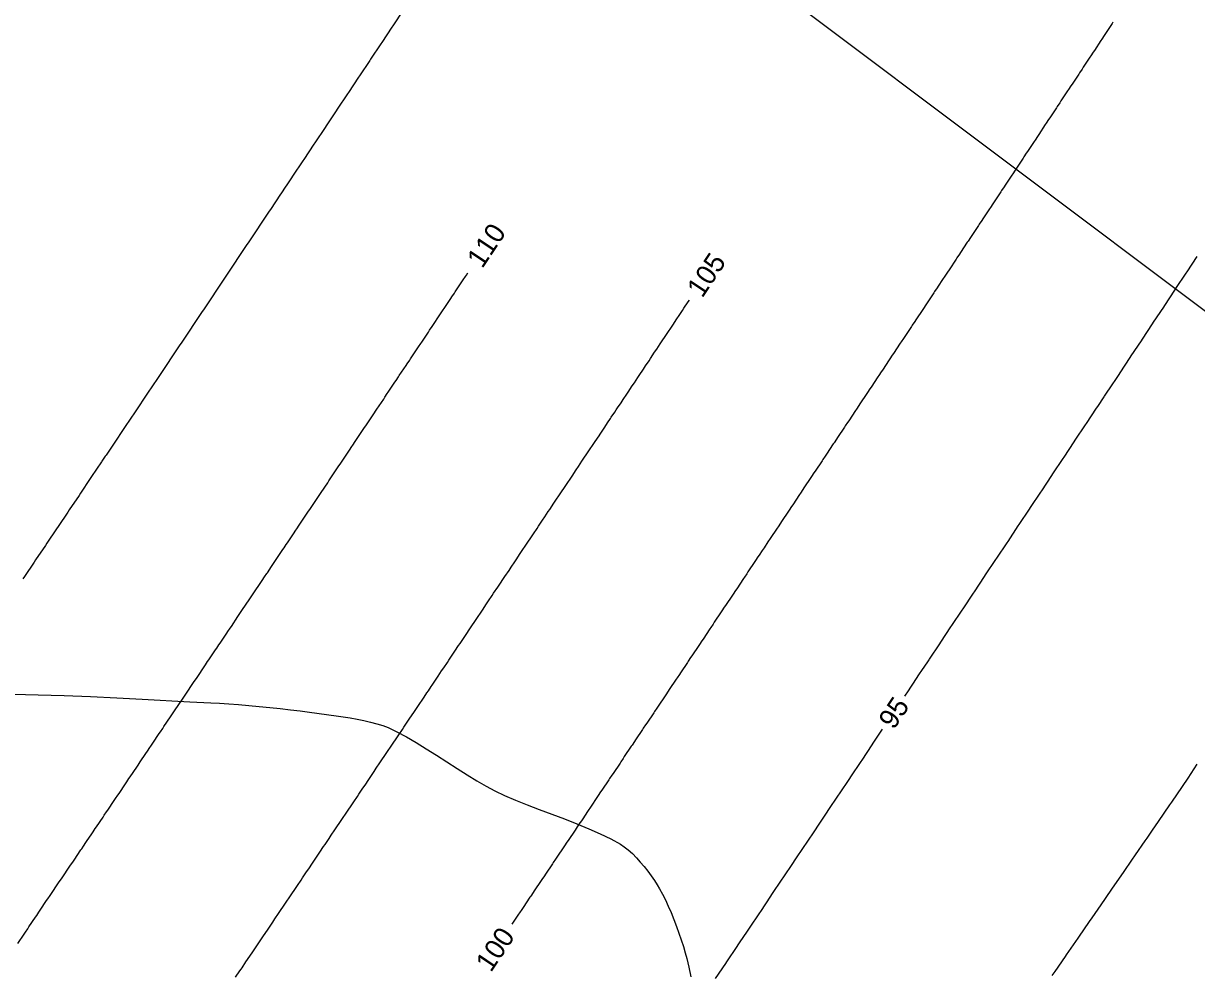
# Model space of a CAD drawing. Extents: x 1752788 to 1754108, y 472767 to 474963.
# Drawn here: x 1753280 to 1753338.7, y 473789.9 to 473837.4 of the extents above; entities that cross this region are included whole.
import ezdxf

# ---------------------------------------------------------------- set-up
doc = ezdxf.new("R2010")
doc.units = 0
for name, color, linetype in [('D_Roadway_Centerline', 7, 'Continuous'), ('D_Slope_ClearingLimitLine', 7, 'Continuous'), ('Default', 7, 'Continuous'), ('M_Drainage_Ditch_Line', 7, 'Continuous'), ('S_Contours_Major', 7, 'Continuous')]:
    doc.layers.add(name, color=color, linetype=linetype)

msp = doc.modelspace()

# ---------------------------------------------------------------- linework, layer by layer
at = {"layer": 'D_Roadway_Centerline'}
msp.add_arc((1748084.974, 477769.754), 6500, 316.3419444, 334.4169444, dxfattribs=at)
at = {"layer": 'D_Slope_ClearingLimitLine'}
msp.add_lwpolyline([(1753331.481, 473789.723), (1753331.626, 473789.934), (1753332.145, 473790.688), (1753332.2, 473790.768), (1753332.774, 473791.602), (1753332.81, 473791.653), (1753333.349, 473792.436), (1753333.474, 473792.618), (1753333.923, 473793.27), (1753334.139, 473793.583), (1753334.498, 473794.104), (1753334.803, 473794.548), (1753335.072, 473794.938), (1753335.468, 473795.513), (1753335.646, 473795.772), (1753336.132, 473796.478), (1753336.221, 473796.606), (1753336.495, 473797.004), (1753336.795, 473797.44), (1753336.797, 473797.443), (1753337.369, 473798.274), (1753337.461, 473798.408), (1753338, 473799.19), (1753338.276, 473799.608), (1753338.723, 473800.31)], dxfattribs=at)
at = {"layer": 'Default'}
msp.add_line((1753227.691, 473906.713), (1753342.696, 473820.324), dxfattribs=at)
at = {"layer": 'M_Drainage_Ditch_Line'}
msp.add_lwpolyline([(1753279.464, 473803.81), (1753280.738, 473803.789), (1753282.043, 473803.749), (1753283.358, 473803.696), (1753284.664, 473803.633), (1753285.939, 473803.567), (1753288.317, 473803.438), (1753289.381, 473803.386), (1753289.808, 473803.363), (1753290.272, 473803.332), (1753290.763, 473803.295), (1753291.274, 473803.251), (1753291.797, 473803.203), (1753292.324, 473803.15), (1753292.847, 473803.095), (1753293.357, 473803.038), (1753293.846, 473802.98), (1753294.307, 473802.921), (1753295.652, 473802.736), (1753295.993, 473802.685), (1753296.341, 473802.629), (1753296.691, 473802.567), (1753297.035, 473802.498), (1753297.369, 473802.422), (1753297.686, 473802.337), (1753297.98, 473802.243), (1753298.246, 473802.139), (1753298.691, 473801.926), (1753299.162, 473801.673), (1753299.653, 473801.388), (1753300.158, 473801.078), (1753300.671, 473800.754), (1753301.698, 473800.096), (1753302.199, 473799.778), (1753302.685, 473799.481), (1753303.149, 473799.212), (1753303.585, 473798.98), (1753304.076, 473798.748), (1753304.619, 473798.515), (1753305.201, 473798.281), (1753305.81, 473798.046), (1753307.065, 473797.569), (1753307.687, 473797.325), (1753308.29, 473797.078), (1753308.863, 473796.827), (1753309.392, 473796.57), (1753309.868, 473796.309), (1753310.064, 473796.177), (1753310.265, 473796.017), (1753310.467, 473795.832), (1753310.668, 473795.629), (1753310.865, 473795.41), (1753311.056, 473795.183), (1753311.239, 473794.95), (1753311.41, 473794.717), (1753311.568, 473794.489), (1753311.71, 473794.271), (1753311.834, 473794.067), (1753311.977, 473793.806), (1753312.121, 473793.517), (1753312.265, 473793.205), (1753312.407, 473792.877), (1753312.544, 473792.537), (1753312.676, 473792.192), (1753312.8, 473791.847), (1753312.915, 473791.508), (1753313.019, 473791.18), (1753313.11, 473790.87), (1753313.187, 473790.582), (1753313.289, 473790.142), (1753313.388, 473789.663)], dxfattribs=at)
at = {"layer": 'S_Contours_Major'}
for points in [[(1753298.996, 473838.055), (1753298.482, 473837.282), (1753298.439, 473837.216), (1753297.926, 473836.445), (1753297.881, 473836.378), (1753297.369, 473835.608), (1753297.324, 473835.539), (1753296.813, 473834.771), (1753296.766, 473834.701), (1753296.256, 473833.934), (1753296.208, 473833.863), (1753295.699, 473833.098), (1753295.651, 473833.025), (1753295.142, 473832.261), (1753295.093, 473832.187), (1753294.585, 473831.424), (1753294.534, 473831.349), (1753294.027, 473830.588), (1753293.976, 473830.511), (1753293.47, 473829.751), (1753293.418, 473829.673), (1753293.151, 473829.273), (1753293.131, 473829.243), (1753292.883, 473828.871), (1753292.864, 473828.843), (1753292.354, 473828.079), (1753292.3, 473827.998), (1753291.797, 473827.243), (1753291.742, 473827.16), (1753291.239, 473826.407), (1753291.183, 473826.323), (1753290.68, 473825.571), (1753290.624, 473825.486), (1753290.122, 473824.735), (1753290.064, 473824.648), (1753289.564, 473823.899), (1753289.505, 473823.811), (1753289.005, 473823.063), (1753288.946, 473822.974), (1753288.446, 473822.227), (1753288.386, 473822.137), (1753287.888, 473821.392), (1753287.826, 473821.3), (1753287.329, 473820.556), (1753287.266, 473820.463), (1753286.77, 473819.721), (1753286.706, 473819.626), (1753286.21, 473818.885), (1753286.146, 473818.789), (1753285.651, 473818.05), (1753285.586, 473817.953), (1753285.091, 473817.214), (1753285.025, 473817.116), (1753284.532, 473816.379), (1753284.465, 473816.279), (1753284.135, 473815.788), (1753284.094, 473815.727), (1753283.929, 473815.48), (1753283.912, 473815.455), (1753283.412, 473814.709), (1753283.343, 473814.607), (1753282.852, 473813.874), (1753282.782, 473813.77), (1753282.291, 473813.039), (1753282.221, 473812.934), (1753281.731, 473812.204), (1753281.66, 473812.098), (1753281.17, 473811.369), (1753281.099, 473811.262), (1753280.61, 473810.534), (1753280.537, 473810.426), (1753280.049, 473809.699), (1753279.976, 473809.59)], [(1753334.516, 473837.452), (1753334.475, 473837.39), (1753334.145, 473836.891), (1753334.084, 473836.797), (1753333.96, 473836.609), (1753333.918, 473836.547), (1753333.588, 473836.047), (1753333.526, 473835.953), (1753333.403, 473835.766), (1753333.362, 473835.704), (1753333.031, 473835.204), (1753332.969, 473835.11), (1753332.846, 473834.924), (1753332.805, 473834.861), (1753332.474, 473834.36), (1753332.412, 473834.267), (1753332.289, 473834.081), (1753332.248, 473834.019), (1753331.916, 473833.517), (1753331.855, 473833.424), (1753331.732, 473833.238), (1753331.691, 473833.176), (1753331.358, 473832.674), (1753331.297, 473832.581), (1753331.174, 473832.395), (1753331.133, 473832.334), (1753330.8, 473831.83), (1753330.739, 473831.738), (1753330.617, 473831.553), (1753330.576, 473831.491), (1753330.243, 473830.987), (1753330.181, 473830.895), (1753330.059, 473830.71), (1753330.019, 473830.649), (1753329.684, 473830.144), (1753329.623, 473830.052), (1753329.502, 473829.868), (1753329.461, 473829.806), (1753329.126, 473829.301), (1753329.065, 473829.209), (1753328.944, 473829.026), (1753328.903, 473828.964), (1753328.568, 473828.458), (1753328.507, 473828.367), (1753328.386, 473828.183), (1753328.345, 473828.122), (1753328.009, 473827.616), (1753327.949, 473827.524), (1753327.828, 473827.341), (1753327.787, 473827.28), (1753327.451, 473826.773), (1753327.39, 473826.682), (1753327.269, 473826.499), (1753327.229, 473826.439), (1753326.892, 473825.93), (1753326.832, 473825.839), (1753326.711, 473825.657), (1753326.671, 473825.597), (1753326.313, 473825.057), (1753326.237, 473824.944), (1753326.103, 473824.741), (1753325.99, 473824.571), (1753325.774, 473824.245), (1753325.714, 473824.155), (1753325.594, 473823.974), (1753325.554, 473823.914), (1753325.215, 473823.403), (1753325.155, 473823.313), (1753325.035, 473823.132), (1753324.995, 473823.072), (1753324.655, 473822.561), (1753324.596, 473822.471), (1753324.476, 473822.291), (1753324.436, 473822.231), (1753324.096, 473821.718), (1753324.036, 473821.629), (1753323.917, 473821.449), (1753323.877, 473821.389), (1753323.536, 473820.876), (1753323.477, 473820.787), (1753323.358, 473820.608), (1753323.318, 473820.548), (1753322.977, 473820.034), (1753322.917, 473819.945), (1753322.799, 473819.766), (1753322.759, 473819.707), (1753322.417, 473819.192), (1753322.358, 473819.103), (1753322.239, 473818.925), (1753322.2, 473818.866), (1753321.857, 473818.35), (1753321.798, 473818.261), (1753321.68, 473818.084), (1753321.64, 473818.025), (1753321.297, 473817.508), (1753321.238, 473817.42), (1753321.12, 473817.243), (1753321.081, 473817.184), (1753320.736, 473816.666), (1753320.678, 473816.578), (1753320.56, 473816.402), (1753320.521, 473816.343), (1753320.176, 473815.825), (1753320.117, 473815.737), (1753320, 473815.56), (1753319.961, 473815.501), (1753319.616, 473814.983), (1753319.557, 473814.895), (1753319.439, 473814.719), (1753319.4, 473814.66), (1753319.055, 473814.142), (1753318.996, 473814.054), (1753318.878, 473813.877), (1753318.839, 473813.818), (1753318.494, 473813.301), (1753318.435, 473813.212), (1753318.317, 473813.035), (1753318.278, 473812.976), (1753317.933, 473812.459), (1753317.874, 473812.371), (1753317.756, 473812.193), (1753317.717, 473812.134), (1753317.363, 473811.604), (1753317.25, 473811.434), (1753317.06, 473811.15), (1753316.966, 473811.008), (1753316.811, 473810.777), (1753316.752, 473810.688), (1753316.634, 473810.511), (1753316.595, 473810.452), (1753316.25, 473809.936), (1753316.191, 473809.847), (1753316.073, 473809.671), (1753316.033, 473809.612), (1753315.688, 473809.095), (1753315.629, 473809.006), (1753315.512, 473808.83), (1753315.472, 473808.771), (1753315.127, 473808.254), (1753315.068, 473808.166), (1753314.95, 473807.989), (1753314.911, 473807.93), (1753314.565, 473807.413), (1753314.506, 473807.325), (1753314.389, 473807.149), (1753314.349, 473807.09), (1753314.003, 473806.572), (1753313.944, 473806.484), (1753313.827, 473806.308), (1753313.788, 473806.25), (1753313.441, 473805.731), (1753313.382, 473805.644), (1753313.265, 473805.468), (1753313.226, 473805.409), (1753312.879, 473804.891), (1753312.82, 473804.803), (1753312.703, 473804.628), (1753312.664, 473804.569), (1753312.317, 473804.05), (1753312.258, 473803.963), (1753312.141, 473803.787), (1753312.102, 473803.729), (1753311.754, 473803.21), (1753311.696, 473803.122), (1753311.579, 473802.947), (1753311.54, 473802.889), (1753311.192, 473802.369), (1753311.133, 473802.282), (1753311.016, 473802.107), (1753310.977, 473802.049), (1753310.629, 473801.529), (1753310.571, 473801.442), (1753310.454, 473801.267), (1753310.415, 473801.209), (1753310.066, 473800.689), (1753310.008, 473800.602), (1753309.891, 473800.427), (1753309.852, 473800.369), (1753309.503, 473799.849), (1753309.445, 473799.762), (1753309.328, 473799.588), (1753309.29, 473799.53), (1753308.94, 473799.009), (1753308.882, 473798.922), (1753308.765, 473798.747), (1753308.726, 473798.689), (1753308.371, 473798.159), (1753308.253, 473797.984), (1753308.227, 473797.945), (1753307.982, 473797.579), (1753307.917, 473797.482), (1753307.794, 473797.3), (1753307.657, 473797.095), (1753307.599, 473797.008), (1753307.251, 473796.489), (1753307.192, 473796.401), (1753307.074, 473796.226), (1753307.034, 473796.167), (1753306.687, 473795.65), (1753306.628, 473795.562), (1753306.51, 473795.385), (1753306.47, 473795.326), (1753306.123, 473794.81), (1753306.064, 473794.722), (1753305.945, 473794.545), (1753305.906, 473794.486), (1753305.56, 473793.971), (1753305.5, 473793.882), (1753305.381, 473793.705), (1753305.341, 473793.646), (1753304.996, 473793.131), (1753304.936, 473793.042), (1753304.817, 473792.865), (1753304.777, 473792.805), (1753304.439, 473792.302)], [(1753324.097, 473803.712), (1753324.162, 473803.809), (1753324.213, 473803.885), (1753324.724, 473804.651), (1753324.775, 473804.727), (1753325.021, 473805.096), (1753325.039, 473805.123), (1753325.313, 473805.534), (1753325.333, 473805.563), (1753325.849, 473806.336), (1753325.899, 473806.412), (1753326.411, 473807.18), (1753326.461, 473807.254), (1753326.973, 473808.023), (1753327.022, 473808.096), (1753327.535, 473808.867), (1753327.584, 473808.939), (1753328.097, 473809.71), (1753328.145, 473809.782), (1753328.659, 473810.553), (1753328.706, 473810.624), (1753329.219, 473811.395), (1753329.267, 473811.467), (1753329.78, 473812.238), (1753329.828, 473812.311), (1753330.341, 473813.08), (1753330.389, 473813.154), (1753330.901, 473813.923), (1753330.95, 473813.997), (1753331.461, 473814.766), (1753331.511, 473814.84), (1753332.021, 473815.608), (1753332.071, 473815.684), (1753332.581, 473816.451), (1753332.632, 473816.527), (1753333.141, 473817.294), (1753333.192, 473817.371), (1753333.701, 473818.137), (1753333.752, 473818.215), (1753334.072, 473818.696), (1753334.098, 473818.736), (1753334.292, 473819.028), (1753334.306, 473819.049), (1753334.82, 473819.824), (1753334.872, 473819.902), (1753335.379, 473820.667), (1753335.432, 473820.746), (1753335.939, 473821.51), (1753335.991, 473821.59), (1753336.498, 473822.354), (1753336.551, 473822.434), (1753337.057, 473823.197), (1753337.11, 473823.278), (1753337.615, 473824.041), (1753337.669, 473824.122), (1753338.174, 473824.885), (1753338.228, 473824.967), (1753338.733, 473825.728)], [(1753279.713, 473791.334), (1753280.032, 473791.807), (1753280.099, 473791.906), (1753280.21, 473792.07), (1753280.276, 473792.169), (1753280.596, 473792.643), (1753280.663, 473792.741), (1753280.773, 473792.905), (1753280.84, 473793.004), (1753281.16, 473793.479), (1753281.227, 473793.577), (1753281.337, 473793.741), (1753281.403, 473793.839), (1753281.725, 473794.315), (1753281.791, 473794.413), (1753281.901, 473794.576), (1753281.967, 473794.674), (1753282.288, 473795.151), (1753282.354, 473795.249), (1753282.464, 473795.411), (1753282.53, 473795.509), (1753282.878, 473796.026), (1753282.915, 473796.08), (1753282.997, 473796.202), (1753283.121, 473796.386), (1753283.157, 473796.439), (1753283.416, 473796.823), (1753283.481, 473796.92), (1753283.59, 473797.082), (1753283.656, 473797.179), (1753283.98, 473797.66), (1753284.045, 473797.756), (1753284.153, 473797.918), (1753284.219, 473798.014), (1753284.543, 473798.496), (1753284.608, 473798.593), (1753284.716, 473798.753), (1753284.781, 473798.85), (1753285.106, 473799.333), (1753285.171, 473799.429), (1753285.279, 473799.589), (1753285.344, 473799.685), (1753285.669, 473800.169), (1753285.734, 473800.265), (1753285.842, 473800.425), (1753285.906, 473800.521), (1753286.232, 473801.006), (1753286.297, 473801.101), (1753286.404, 473801.261), (1753286.468, 473801.356), (1753286.795, 473801.843), (1753286.859, 473801.938), (1753286.966, 473802.097), (1753287.03, 473802.192), (1753287.358, 473802.679), (1753287.422, 473802.774), (1753287.529, 473802.933), (1753287.593, 473803.028), (1753287.921, 473803.516), (1753287.984, 473803.611), (1753288.091, 473803.77), (1753288.155, 473803.865), (1753288.483, 473804.353), (1753288.547, 473804.448), (1753288.653, 473804.606), (1753288.717, 473804.701), (1753289.045, 473805.19), (1753289.109, 473805.285), (1753289.215, 473805.443), (1753289.279, 473805.538), (1753289.607, 473806.027), (1753289.671, 473806.122), (1753289.777, 473806.28), (1753289.841, 473806.374), (1753290.169, 473806.864), (1753290.233, 473806.959), (1753290.339, 473807.116), (1753290.402, 473807.211), (1753290.731, 473807.701), (1753290.795, 473807.796), (1753290.9, 473807.953), (1753290.964, 473808.048), (1753291.293, 473808.539), (1753291.356, 473808.633), (1753291.462, 473808.79), (1753291.525, 473808.885), (1753291.876, 473809.408), (1753291.946, 473809.512), (1753292.062, 473809.686), (1753292.175, 473809.853), (1753292.203, 473809.895), (1753292.416, 473810.214), (1753292.479, 473810.308), (1753292.585, 473810.465), (1753292.648, 473810.559), (1753292.978, 473811.051), (1753293.041, 473811.145), (1753293.145, 473811.302), (1753293.208, 473811.395), (1753293.539, 473811.889), (1753293.602, 473811.982), (1753293.706, 473812.139), (1753293.769, 473812.232), (1753294.1, 473812.727), (1753294.163, 473812.82), (1753294.267, 473812.976), (1753294.329, 473813.069), (1753294.661, 473813.564), (1753294.723, 473813.658), (1753294.827, 473813.813), (1753294.89, 473813.906), (1753295.222, 473814.402), (1753295.284, 473814.495), (1753295.388, 473814.65), (1753295.45, 473814.743), (1753295.783, 473815.24), (1753295.844, 473815.333), (1753295.948, 473815.487), (1753296.01, 473815.58), (1753296.343, 473816.078), (1753296.405, 473816.171), (1753296.508, 473816.324), (1753296.569, 473816.417), (1753296.904, 473816.917), (1753296.965, 473817.009), (1753297.068, 473817.162), (1753297.129, 473817.254), (1753297.464, 473817.755), (1753297.525, 473817.847), (1753297.648, 473818.03), (1753297.689, 473818.091), (1753298.024, 473818.593), (1753298.085, 473818.685), (1753298.207, 473818.867), (1753298.248, 473818.928), (1753298.584, 473819.431), (1753298.645, 473819.523), (1753298.767, 473819.705), (1753298.807, 473819.766), (1753299.144, 473820.27), (1753299.205, 473820.361), (1753299.326, 473820.543), (1753299.367, 473820.603), (1753299.704, 473821.108), (1753299.764, 473821.199), (1753299.885, 473821.38), (1753299.926, 473821.441), (1753300.263, 473821.947), (1753300.324, 473822.037), (1753300.444, 473822.218), (1753300.485, 473822.278), (1753300.833, 473822.801), (1753300.939, 473822.959), (1753301.11, 473823.217), (1753301.215, 473823.373), (1753301.382, 473823.625), (1753301.442, 473823.714), (1753301.562, 473823.894), (1753301.602, 473823.954), (1753301.942, 473824.463), (1753302.001, 473824.553), (1753302.121, 473824.732), (1753302.161, 473824.792), (1753302.239, 473824.909)], [(1753290.614, 473789.642), (1753290.825, 473789.956), (1753290.885, 473790.045), (1753290.936, 473790.121), (1753291.133, 473790.412), (1753291.216, 473790.536), (1753291.355, 473790.742), (1753291.439, 473790.866), (1753291.605, 473791.113), (1753291.674, 473791.214), (1753291.742, 473791.316), (1753291.913, 473791.57), (1753292.016, 473791.723), (1753292.203, 473792), (1753292.272, 473792.102), (1753292.478, 473792.408), (1753292.58, 473792.56), (1753292.767, 473792.837), (1753292.836, 473792.939), (1753293.042, 473793.245), (1753293.145, 473793.398), (1753293.331, 473793.674), (1753293.399, 473793.776), (1753293.606, 473794.083), (1753293.709, 473794.236), (1753293.894, 473794.511), (1753293.963, 473794.614), (1753294.169, 473794.92), (1753294.273, 473795.074), (1753294.458, 473795.348), (1753294.526, 473795.451), (1753294.733, 473795.758), (1753294.836, 473795.912), (1753295.021, 473796.186), (1753295.09, 473796.288), (1753295.297, 473796.596), (1753295.4, 473796.75), (1753295.584, 473797.024), (1753295.653, 473797.126), (1753295.86, 473797.434), (1753295.964, 473797.588), (1753296.148, 473797.862), (1753296.217, 473797.964), (1753296.423, 473798.272), (1753296.527, 473798.426), (1753296.711, 473798.7), (1753296.78, 473798.802), (1753296.987, 473799.11), (1753297.09, 473799.264), (1753297.274, 473799.538), (1753297.343, 473799.641), (1753297.55, 473799.949), (1753297.653, 473800.103), (1753297.837, 473800.377), (1753297.906, 473800.479), (1753298.113, 473800.787), (1753298.216, 473800.941), (1753298.4, 473801.215), (1753298.469, 473801.318), (1753298.676, 473801.625), (1753298.779, 473801.779), (1753298.963, 473802.054), (1753299.032, 473802.156), (1753299.238, 473802.464), (1753299.341, 473802.618), (1753299.526, 473802.893), (1753299.595, 473802.995), (1753299.629, 473803.046), (1753299.835, 473803.354), (1753299.942, 473803.513), (1753300.045, 473803.666), (1753300.191, 473803.885), (1753300.26, 473803.987), (1753300.398, 473804.192), (1753300.443, 473804.261), (1753300.617, 473804.519), (1753300.685, 473804.622), (1753300.754, 473804.724), (1753300.925, 473804.98), (1753301.028, 473805.133), (1753301.213, 473805.409), (1753301.282, 473805.511), (1753301.488, 473805.819), (1753301.591, 473805.972), (1753301.775, 473806.247), (1753301.844, 473806.35), (1753302.05, 473806.658), (1753302.153, 473806.811), (1753302.336, 473807.086), (1753302.405, 473807.188), (1753302.611, 473807.496), (1753302.715, 473807.65), (1753302.898, 473807.924), (1753302.967, 473808.027), (1753303.173, 473808.335), (1753303.276, 473808.49), (1753303.459, 473808.763), (1753303.528, 473808.866), (1753303.735, 473809.174), (1753303.838, 473809.329), (1753304.02, 473809.601), (1753304.089, 473809.704), (1753304.296, 473810.014), (1753304.399, 473810.168), (1753304.581, 473810.44), (1753304.65, 473810.543), (1753304.857, 473810.853), (1753304.961, 473811.008), (1753305.142, 473811.279), (1753305.211, 473811.382), (1753305.418, 473811.692), (1753305.522, 473811.847), (1753305.703, 473812.117), (1753305.772, 473812.221), (1753305.979, 473812.531), (1753306.083, 473812.687), (1753306.263, 473812.956), (1753306.333, 473813.06), (1753306.54, 473813.371), (1753306.644, 473813.526), (1753306.824, 473813.795), (1753306.893, 473813.899), (1753307.101, 473814.21), (1753307.205, 473814.366), (1753307.384, 473814.634), (1753307.454, 473814.738), (1753307.662, 473815.05), (1753307.766, 473815.206), (1753307.944, 473815.473), (1753308.014, 473815.577), (1753308.222, 473815.89), (1753308.326, 473816.046), (1753308.504, 473816.313), (1753308.574, 473816.417), (1753308.609, 473816.469), (1753308.8, 473816.756), (1753308.851, 473816.832), (1753308.952, 473816.984), (1753309.085, 473817.183), (1753309.232, 473817.404), (1753309.377, 473817.622), (1753309.414, 473817.676), (1753309.589, 473817.939), (1753309.659, 473818.044), (1753309.729, 473818.148), (1753309.903, 473818.409), (1753310.007, 473818.566), (1753310.184, 473818.831), (1753310.254, 473818.936), (1753310.463, 473819.249), (1753310.567, 473819.406), (1753310.744, 473819.671), (1753310.814, 473819.776), (1753311.023, 473820.089), (1753311.127, 473820.246), (1753311.304, 473820.512), (1753311.373, 473820.616), (1753311.582, 473820.93), (1753311.687, 473821.086), (1753311.863, 473821.351), (1753311.933, 473821.456), (1753312.142, 473821.77), (1753312.246, 473821.927), (1753312.422, 473822.191), (1753312.492, 473822.296), (1753312.701, 473822.61), (1753312.806, 473822.767), (1753312.981, 473823.031), (1753313.051, 473823.136), (1753313.26, 473823.451), (1753313.323, 473823.545)], [(1753314.635, 473789.579), (1753315.145, 473790.339), (1753315.199, 473790.42), (1753315.71, 473791.181), (1753315.763, 473791.26), (1753315.932, 473791.511), (1753315.944, 473791.53), (1753316.296, 473792.054), (1753316.324, 473792.097), (1753316.841, 473792.866), (1753316.891, 473792.942), (1753317.405, 473793.708), (1753317.455, 473793.783), (1753317.969, 473794.549), (1753318.019, 473794.625), (1753318.532, 473795.391), (1753318.583, 473795.466), (1753319.096, 473796.232), (1753319.146, 473796.308), (1753319.659, 473797.074), (1753319.71, 473797.149), (1753320.223, 473797.915), (1753320.273, 473797.991), (1753320.786, 473798.757), (1753320.836, 473798.833), (1753321.349, 473799.599), (1753321.399, 473799.674), (1753321.912, 473800.441), (1753321.962, 473800.516), (1753322.475, 473801.282), (1753322.525, 473801.358), (1753322.991, 473802.055)]]:
    msp.add_lwpolyline(points, dxfattribs=at)

# ---------------------------------------------------------------- texts
for s, rotation, p in [('110', 56.33191, (1753302.956, 473825.088)), ('105', 56.37592, (1753313.965, 473823.611)), ('95', 56.2621, (1753323.551, 473801.997)), ('100', 56.0792, (1753303.389, 473789.85))]:
    msp.add_text(s, height=0.996, rotation=rotation, dxfattribs=at).set_placement(p)

doc.saveas('drawing.dxf')
